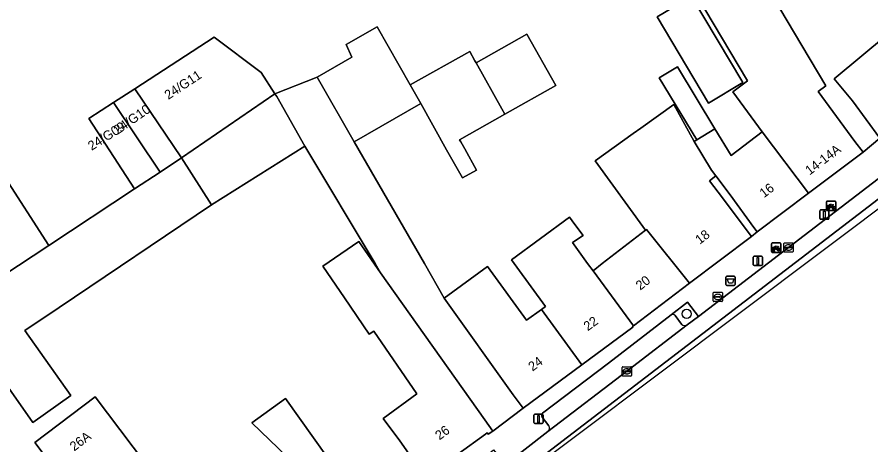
# Model space of a CAD drawing. Extents: x 159371 to 159986, y 382987 to 383597.
# Drawn here: x 159845.8 to 159937.1, y 383230.6 to 383276.3 of the extents above; entities that cross this region are included whole.
import ezdxf

# ---------------------------------------------------------------- set-up
doc = ezdxf.new("R2010")
doc.units = 0
for name, color, linetype in [('IMGEO_Afvalbak', 7, 'Continuous'), ('IMGEO_Boom', 7, 'Continuous'), ('IMGEO_Erf', 7, 'Continuous'), ('IMGEO_Fietsenrek', 7, 'Continuous'), ('IMGEO_Groenvoorziening', 7, 'Continuous'), ('IMGEO_Kolk', 7, 'Continuous'), ('IMGEO_Lichtmast', 7, 'Continuous'), ('IMGEO_Pand', 7, 'Continuous'), ('IMGEO_Pand_nummerreeks', 7, 'Continuous'), ('IMGEO_Parkeervlak_open', 7, 'Continuous'), ('IMGEO_Rijbaan_lokaal_gesloten', 7, 'Continuous'), ('IMGEO_Rijbaan_lokaal_open', 7, 'Continuous'), ('IMGEO_Voetpad_open', 7, 'Continuous')]:
    doc.layers.add(name, color=color, linetype=linetype)

msp = doc.modelspace()

# ---------------------------------------------------------------- linework, layer by layer
at = {"layer": 'IMGEO_Afvalbak'}
for p, q in [((159921.6, 383247.75), (159921.6, 383248.55)), ((159921.6, 383248.55), (159921.6, 383247.75)), ((159921.7, 383248.65), (159922.49, 383248.65)), ((159922.49, 383248.65), (159921.7, 383248.65)), ((159922.59, 383248.55), (159922.59, 383247.75)), ((159922.59, 383247.75), (159922.59, 383248.55)), ((159922.49, 383247.65), (159921.7, 383247.65)), ((159921.7, 383247.65), (159922.49, 383247.65))]:
    msp.add_line(p, q, dxfattribs=at)
msp.add_lwpolyline([(159921.743, 383248.364), (159922.447, 383248.364), (159922.298, 383247.894), (159921.892, 383247.894), (159921.743, 383248.364)], dxfattribs=at)
for centre, start, end in [((159921.7, 383248.55), 90, 180), ((159921.7, 383248.55), 90, 180), ((159922.49, 383248.55), 0, 90), ((159922.49, 383248.55), 360, 90), ((159921.7, 383247.75), 180, 270), ((159921.7, 383247.75), 180, 270), ((159922.49, 383247.75), 270, 0), ((159922.49, 383247.75), 270, 0)]:
    msp.add_arc(centre, 0.1, start, end, dxfattribs=at)
at = {"layer": 'IMGEO_Boom'}
msp.add_circle((159917.394, 383244.613), 0.489, dxfattribs=at)
at = {"layer": 'IMGEO_Erf'}
for points in [[(159916.391, 383295.732), (159929.731, 383273.294), (159932.286, 383268.996), (159931.449, 383268.361), (159935.394, 383263.043), (159936.262, 383261.889), (159938.069, 383263.392), (159935.149, 383267.369), (159933.181, 383269.745), (159938.884, 383274.471)], [(159888.942, 383267.107), (159881.821, 383262.989), (159889.333, 383250), (159891.454, 383246.285), (159896.094, 383249.664), (159900.273, 383243.925), (159901.857, 383245.074), (159902.302, 383245.397), (159899.218, 383249.602), (159898.643, 383250.386), (159904.87, 383254.952), (159905.444, 383254.169), (159906.311, 383252.986), (159905.181, 383252.229), (159906.797, 383250), (159907.379, 383249.229), (159908.37, 383250), (159913, 383253.565), (159907.607, 383260.971), (159911.671, 383263.885), (159912.475, 383264.462), (159916.013, 383266.999), (159918.196, 383263.04), (159918.468, 383263.205), (159914.449, 383269.835), (159916.408, 383271.023), (159920.427, 383264.392), (159922.151, 383261.548), (159925.461, 383264.06), (159922.328, 383268.339), (159923.904, 383269.535), (159910.435, 383292.191)], [(159844.202, 383259.616), (159849.15, 383251.931), (159858.332, 383257.968), (159853.456, 383265.492), (159856.082, 383267.195), (159858.36, 383268.671), (159866.841, 383274.168), (159871.87, 383270.393), (159873.352, 383268.134), (159877.865, 383269.907), (159881.58, 383272.032), (159880.954, 383273.399), (159884.279, 383275.3), (159887.828, 383269.093), (159894.183, 383272.656), (159894.739, 383271.664), (159894.863, 383271.443), (159900.315, 383274.499), (159903.396, 383269.004), (159897.944, 383265.948), (159893.093, 383263.229), (159893.222, 383262.999), (159893.65, 383262.236), (159894.913, 383259.983), (159893.409, 383259.139), (159891.718, 383262.155), (159888.942, 383267.107)], [(159889.569, 383226.993), (159886.701, 383231.03), (159884.934, 383233.432), (159888.517, 383236.07), (159883.921, 383242.774), (159883.447, 383242.45), (159880.783, 383246.335), (159878.465, 383249.715), (159882.326, 383252.361), (159884.643, 383248.981), (159884.072, 383250), (159876.558, 383262.55), (159866.58, 383256.276), (159850.254, 383245.306), (159846.589, 383242.843), (159851.5, 383235.872), (159847.444, 383233.016), (159840.201, 383243.3)], [(159876.562, 383227.528), (159870.877, 383232.977), (159874.49, 383235.552), (159878.98, 383229.251)]]:
    msp.add_lwpolyline(points, dxfattribs=at)
for points in [[(159914.231, 383276.374), (159917.912, 383278.563), (159923.401, 383269.331), (159919.72, 383267.142)], [(159922.053, 383257.339), (159920.52, 383259.358), (159919.823, 383258.822), (159921.228, 383256.998), (159923.862, 383253.482), (159924.314, 383252.884), (159924.928, 383253.367), (159924.582, 383253.827)], [(159854.108, 383235.738), (159860.814, 383226.859), (159854.38, 383222), (159847.675, 383230.879)]]:
    msp.add_lwpolyline(points, close=True, dxfattribs=at)
at = {"layer": 'IMGEO_Fietsenrek'}
for p, q in [((159932.345, 383255.729), (159932.345, 383256.57)), ((159932.345, 383256.57), (159932.345, 383255.729)), ((159932.42, 383256.654), (159933.261, 383256.654)), ((159933.261, 383256.654), (159932.42, 383256.654)), ((159933.345, 383256.579), (159933.345, 383255.738)), ((159933.345, 383255.738), (159933.345, 383256.579)), ((159933.27, 383255.654), (159932.429, 383255.654)), ((159932.429, 383255.654), (159933.27, 383255.654)), ((159932.472, 383255.738), (159932.511, 383255.898)), ((159932.506, 383255.738), (159932.472, 383255.738)), ((159932.541, 383255.886), (159932.506, 383255.738)), ((159932.583, 383255.91), (159932.582, 383255.914)), ((159932.624, 383255.738), (159932.59, 383255.88)), ((159932.614, 383255.921), (159932.615, 383255.914)), ((159932.622, 383255.884), (159932.657, 383255.738)), ((159932.657, 383255.738), (159932.624, 383255.738)), ((159933.032, 383256.203), (159933.068, 383256.108)), ((159926.473, 383251.263), (159926.473, 383252.104)), ((159926.473, 383252.104), (159926.473, 383251.263)), ((159926.548, 383252.188), (159927.389, 383252.188)), ((159927.389, 383252.188), (159926.548, 383252.188)), ((159927.473, 383252.113), (159927.473, 383251.272)), ((159927.473, 383251.272), (159927.473, 383252.113)), ((159927.398, 383251.188), (159926.557, 383251.188)), ((159926.557, 383251.188), (159927.398, 383251.188)), ((159926.6, 383251.272), (159926.639, 383251.432)), ((159926.634, 383251.272), (159926.6, 383251.272)), ((159926.669, 383251.42), (159926.634, 383251.272)), ((159926.711, 383251.444), (159926.71, 383251.448)), ((159926.752, 383251.272), (159926.718, 383251.414)), ((159926.742, 383251.455), (159926.743, 383251.448)), ((159926.75, 383251.418), (159926.785, 383251.272)), ((159926.785, 383251.272), (159926.752, 383251.272)), ((159927.16, 383251.737), (159927.196, 383251.642))]:
    msp.add_line(p, q, dxfattribs=at)
for points in [[(159932.679, 383256.128), (159932.627, 383256.038), (159932.587, 383256.013), (159932.588, 383256.06), (159932.643, 383256.154)], [(159932.658, 383256.18), (159932.753, 383256.344), (159932.839, 383256.33), (159932.841, 383256.321), (159932.785, 383256.31), (159932.758, 383256.265), (159933.014, 383256.224)], [(159932.954, 383255.936), (159932.904, 383255.936), (159932.713, 383256.187), (159932.694, 383256.155)], [(159933.001, 383256.199), (159932.744, 383256.24), (159932.727, 383256.211), (159932.894, 383255.991), (159933.001, 383256.199)], [(159933.049, 383256.101), (159933.019, 383256.178), (159932.91, 383255.96), (159932.953, 383255.96)], [(159932.983, 383255.96), (159933.103, 383255.959), (159933.059, 383256.073)], [(159933.079, 383256.08), (159933.134, 383255.935), (159932.984, 383255.935)], [(159933.014, 383256.224), (159933.039, 383256.273), (159933.033, 383256.277), (159933.01, 383256.281), (159932.998, 383256.288), (159932.997, 383256.291), (159932.999, 383256.296), (159933.094, 383256.281), (159933.096, 383256.271), (159933.086, 383256.258), (159933.074, 383256.252), (159933.06, 383256.258), (159933.032, 383256.203)], [(159926.807, 383251.662), (159926.755, 383251.572), (159926.715, 383251.547), (159926.716, 383251.594), (159926.771, 383251.688)], [(159926.786, 383251.714), (159926.881, 383251.878), (159926.967, 383251.864), (159926.969, 383251.855), (159926.913, 383251.844), (159926.886, 383251.799), (159927.142, 383251.758)], [(159927.082, 383251.47), (159927.032, 383251.47), (159926.841, 383251.721), (159926.822, 383251.689)], [(159927.129, 383251.733), (159926.872, 383251.774), (159926.855, 383251.745), (159927.022, 383251.525), (159927.129, 383251.733)], [(159927.177, 383251.635), (159927.147, 383251.712), (159927.038, 383251.494), (159927.081, 383251.494)], [(159927.111, 383251.494), (159927.231, 383251.493), (159927.187, 383251.607)], [(159927.207, 383251.614), (159927.262, 383251.469), (159927.112, 383251.469)], [(159927.142, 383251.758), (159927.167, 383251.807), (159927.161, 383251.811), (159927.138, 383251.815), (159927.126, 383251.822), (159927.125, 383251.825), (159927.127, 383251.83), (159927.222, 383251.815), (159927.224, 383251.805), (159927.214, 383251.792), (159927.202, 383251.786), (159927.188, 383251.792), (159927.16, 383251.737)]]:
    msp.add_lwpolyline(points, dxfattribs=at)
for centre, radius, start, end in [((159932.423, 383256.576), 0.0779, 92.4484, 184.28452), ((159932.423, 383256.576), 0.0779, 92.4484, 184.28452), ((159933.267, 383256.576), 0.0779, 2.4484, 94.28452), ((159933.267, 383256.576), 0.0779, 2.4484, 94.28452), ((159932.423, 383255.732), 0.0779, 182.4484, 274.28452), ((159932.423, 383255.732), 0.0779, 182.4484, 274.28452), ((159932.585, 383256.039), 0.159, 62.67661, 242.13685), ((159932.585, 383256.039), 0.129, 63.31916, 238.90302), ((159932.565, 383255.91), 0.0499, 12.8025, 158.69338), ((159932.585, 383256.039), 0.159, 253.99666, 271.78671), ((159932.565, 383255.91), 0.0174, 12.8025, 163.45023), ((159932.585, 383256.039), 0.129, 253.41502, 269.02044), ((159932.585, 383256.039), 0.129, 283.60429, 43.43025), ((159932.585, 383256.039), 0.159, 283.5766, 46.60424), ((159933.112, 383255.955), 0.159, 113.3408, 178.32165), ((159933.112, 383255.955), 0.159, 187.0065, 105.77075), ((159933.112, 383255.955), 0.129, 113.92302, 177.95563), ((159933.112, 383255.955), 0.129, 188.67146, 104.58832), ((159933.267, 383255.732), 0.0779, 272.4484, 4.28452), ((159933.267, 383255.732), 0.0779, 272.4484, 4.28452), ((159926.551, 383252.11), 0.0779, 92.4484, 184.28452), ((159926.551, 383252.11), 0.0779, 92.4484, 184.28452), ((159927.395, 383252.11), 0.0779, 2.4484, 94.28452), ((159927.395, 383252.11), 0.0779, 2.4484, 94.28452), ((159926.551, 383251.266), 0.0779, 182.4484, 274.28452), ((159926.551, 383251.266), 0.0779, 182.4484, 274.28452), ((159926.713, 383251.573), 0.159, 62.67661, 242.13685), ((159926.713, 383251.573), 0.129, 63.31916, 238.90302), ((159926.693, 383251.444), 0.0499, 12.8025, 158.69338), ((159926.713, 383251.573), 0.159, 253.99666, 271.78671), ((159926.693, 383251.444), 0.0174, 12.8025, 163.45023), ((159926.713, 383251.573), 0.129, 253.41502, 269.02044), ((159926.713, 383251.573), 0.129, 283.60429, 43.43025), ((159926.713, 383251.573), 0.159, 283.5766, 46.60424), ((159927.24, 383251.489), 0.159, 113.3408, 178.32165), ((159927.24, 383251.489), 0.159, 187.0065, 105.77075), ((159927.24, 383251.489), 0.129, 113.92302, 177.95563), ((159927.24, 383251.489), 0.129, 188.67146, 104.58832), ((159927.395, 383251.266), 0.0779, 272.4484, 4.28452), ((159927.395, 383251.266), 0.0779, 272.4484, 4.28452)]:
    msp.add_arc(centre, radius, start, end, dxfattribs=at)
at = {"layer": 'IMGEO_Groenvoorziening'}
for points in [[(159917.448, 383243.448), (159918.678, 383244.335), (159917.468, 383245.881), (159915.741, 383244.492)], [(159916.171, 383244.455), (159916.844, 383243.527)]]:
    msp.add_lwpolyline(points, dxfattribs=at)
for centre, radius, start, end in [((159915.932, 383244.2), 0.349, 46.87499, 123.28903), ((159917.19, 383243.821), 0.454, 220.36899, 304.72764)]:
    msp.add_arc(centre, radius, start, end, dxfattribs=at)
at = {"layer": 'IMGEO_Kolk'}
for p, q in [((159927.79, 383251.279), (159927.79, 383252.131)), ((159927.865, 383252.205), (159928.717, 383252.205)), ((159928.278, 383251.985), (159928.303, 383251.985)), ((159928.791, 383252.131), (159928.791, 383251.279)), ((159928.717, 383251.205), (159927.865, 383251.205)), ((159928.049, 383251.699), (159928.049, 383251.711)), ((159928.487, 383251.662), (159928.089, 383251.662)), ((159928.092, 383251.748), (159928.49, 383251.748)), ((159928.301, 383251.425), (159928.276, 383251.425)), ((159928.533, 383251.711), (159928.533, 383251.699)), ((159920.227, 383246.003), (159920.227, 383246.855)), ((159920.302, 383246.929), (159921.154, 383246.929)), ((159920.529, 383246.472), (159920.927, 383246.472)), ((159920.715, 383246.709), (159920.74, 383246.709)), ((159921.228, 383246.855), (159921.228, 383246.003)), ((159921.154, 383245.929), (159920.302, 383245.929)), ((159920.486, 383246.423), (159920.486, 383246.435)), ((159920.924, 383246.386), (159920.526, 383246.386)), ((159920.738, 383246.149), (159920.713, 383246.149)), ((159920.97, 383246.435), (159920.97, 383246.423)), ((159910.502, 383238.043), (159910.502, 383238.895)), ((159910.577, 383238.969), (159911.429, 383238.969)), ((159910.761, 383238.463), (159910.761, 383238.475)), ((159911.199, 383238.426), (159910.801, 383238.426)), ((159910.804, 383238.512), (159911.202, 383238.512)), ((159910.99, 383238.749), (159911.015, 383238.749)), ((159911.245, 383238.475), (159911.245, 383238.463)), ((159911.503, 383238.895), (159911.503, 383238.043)), ((159911.429, 383237.969), (159910.577, 383237.969)), ((159911.013, 383238.189), (159910.988, 383238.189))]:
    msp.add_line(p, q, dxfattribs=at)
for points in [[(159927.79, 383251.279), (159927.79, 383252.131)], [(159927.865, 383252.205), (159928.717, 383252.205)], [(159928.791, 383252.131), (159928.791, 383251.279)], [(159928.717, 383251.205), (159927.865, 383251.205)], [(159920.227, 383246.003), (159920.227, 383246.855)], [(159920.302, 383246.929), (159921.154, 383246.929)], [(159921.228, 383246.855), (159921.228, 383246.003)], [(159921.154, 383245.929), (159920.302, 383245.929)], [(159910.502, 383238.043), (159910.502, 383238.895)], [(159910.577, 383238.969), (159911.429, 383238.969)], [(159911.503, 383238.895), (159911.503, 383238.043)], [(159911.429, 383237.969), (159910.577, 383237.969)]]:
    msp.add_lwpolyline(points, dxfattribs=at)
for centre, radius, start, end in [((159927.867, 383252.129), 0.0765, 91.55205, 178.44795), ((159927.867, 383252.129), 0.0765, 91.55205, 178.44795), ((159928.715, 383252.129), 0.0765, 1.55205, 88.44795), ((159928.715, 383252.129), 0.0765, 1.55205, 88.44795), ((159927.867, 383251.281), 0.0765, 181.55205, 268.44795), ((159927.867, 383251.281), 0.0765, 181.55205, 268.44795), ((159928.089, 383251.708), 0.0403, 85.87752, 175.75265), ((159928.086, 383251.698), 0.0366, 178.93798, 274.71019), ((159928.49, 383251.705), 0.043, 264.86636, 352.45326), ((159928.494, 383251.71), 0.0386, 1.73085, 96.63898), ((159928.715, 383251.281), 0.0765, 271.55205, 358.44795), ((159928.715, 383251.281), 0.0765, 271.55205, 358.44795), ((159920.304, 383246.853), 0.0765, 91.55205, 178.44795), ((159920.304, 383246.853), 0.0765, 91.55205, 178.44795), ((159920.526, 383246.432), 0.0403, 85.87752, 175.75265), ((159920.931, 383246.434), 0.0386, 1.73085, 96.63898), ((159921.152, 383246.853), 0.0765, 1.55205, 88.44795), ((159921.152, 383246.853), 0.0765, 1.55205, 88.44795), ((159920.304, 383246.005), 0.0765, 181.55205, 268.44795), ((159920.304, 383246.005), 0.0765, 181.55205, 268.44795), ((159920.523, 383246.422), 0.0366, 178.93798, 274.71019), ((159920.927, 383246.429), 0.043, 264.86636, 352.45326), ((159921.152, 383246.005), 0.0765, 271.55205, 358.44795), ((159921.152, 383246.005), 0.0765, 271.55205, 358.44795), ((159910.579, 383238.893), 0.0765, 91.55205, 178.44795), ((159910.579, 383238.893), 0.0765, 91.55205, 178.44795), ((159910.801, 383238.472), 0.0403, 85.87752, 175.75265), ((159910.798, 383238.462), 0.0366, 178.93798, 274.71019), ((159911.202, 383238.469), 0.043, 264.86636, 352.45326), ((159911.206, 383238.474), 0.0386, 1.73085, 96.63898), ((159911.427, 383238.893), 0.0765, 1.55205, 88.44795), ((159911.427, 383238.893), 0.0765, 1.55205, 88.44795), ((159910.579, 383238.045), 0.0765, 181.55205, 268.44795), ((159910.579, 383238.045), 0.0765, 181.55205, 268.44795), ((159911.427, 383238.045), 0.0765, 271.55205, 358.44795), ((159911.427, 383238.045), 0.0765, 271.55205, 358.44795)]:
    msp.add_arc(centre, radius, start, end, dxfattribs=at)
for centre, major_axis, ratio, start_param, end_param in [((159928.277, 383251.705), (-0.387, 0.002), 0.722429, 4.712389, 7.853982), ((159928.302, 383251.705), (-0.39, 0.002), 0.717154, 1.570796, 4.712389), ((159920.714, 383246.429), (-0.387, 0.002), 0.722429, 4.712389, 7.853982), ((159920.739, 383246.429), (-0.39, 0.002), 0.717154, 1.570796, 4.712389), ((159910.989, 383238.469), (-0.387, 0.002), 0.722429, 4.712389, 7.853982), ((159911.014, 383238.469), (-0.39, 0.002), 0.717154, 1.570796, 4.712389)]:
    msp.add_ellipse(centre, major_axis=major_axis, ratio=ratio, start_param=start_param, end_param=end_param, dxfattribs=at)
at = {"layer": 'IMGEO_Lichtmast'}
for p, q in [((159931.631, 383254.819), (159931.631, 383255.619)), ((159931.631, 383255.619), (159931.631, 383254.819)), ((159931.731, 383255.719), (159932.521, 383255.719)), ((159932.521, 383255.719), (159931.731, 383255.719)), ((159932.621, 383255.619), (159932.621, 383254.819)), ((159932.621, 383254.819), (159932.621, 383255.619)), ((159932.521, 383254.719), (159931.731, 383254.719)), ((159931.731, 383254.719), (159932.521, 383254.719)), ((159924.506, 383249.871), (159924.506, 383250.671)), ((159924.506, 383250.671), (159924.506, 383249.871)), ((159924.606, 383250.771), (159925.396, 383250.771)), ((159925.396, 383250.771), (159924.606, 383250.771)), ((159925.496, 383250.671), (159925.496, 383249.871)), ((159925.496, 383249.871), (159925.496, 383250.671)), ((159925.396, 383249.771), (159924.606, 383249.771)), ((159924.606, 383249.771), (159925.396, 383249.771)), ((159901.055, 383232.991), (159901.055, 383233.791)), ((159901.055, 383233.791), (159901.055, 383232.991)), ((159901.155, 383233.891), (159901.945, 383233.891)), ((159901.945, 383233.891), (159901.155, 383233.891)), ((159902.045, 383233.791), (159902.045, 383232.991)), ((159902.045, 383232.991), (159902.045, 383233.791)), ((159901.945, 383232.891), (159901.155, 383232.891)), ((159901.155, 383232.891), (159901.945, 383232.891))]:
    msp.add_line(p, q, dxfattribs=at)
for points in [[(159932.051, 383255.594), (159932.201, 383255.594), (159932.201, 383254.844), (159932.051, 383254.844), (159932.051, 383255.594)], [(159924.926, 383250.646), (159925.076, 383250.646), (159925.076, 383249.896), (159924.926, 383249.896), (159924.926, 383250.646)], [(159901.475, 383233.766), (159901.625, 383233.766), (159901.625, 383233.016), (159901.475, 383233.016), (159901.475, 383233.766)]]:
    msp.add_lwpolyline(points, dxfattribs=at)
for centre, start, end in [((159931.731, 383255.619), 90, 180), ((159931.731, 383255.619), 90, 180), ((159932.521, 383255.619), 0, 90), ((159932.521, 383255.619), 360, 90), ((159931.731, 383254.819), 180, 270), ((159931.731, 383254.819), 180, 270), ((159932.521, 383254.819), 270, 0), ((159932.521, 383254.819), 270, 0), ((159924.606, 383250.671), 90, 180), ((159924.606, 383250.671), 90, 180), ((159925.396, 383250.671), 0, 90), ((159925.396, 383250.671), 360, 90), ((159924.606, 383249.871), 180, 270), ((159924.606, 383249.871), 180, 270), ((159925.396, 383249.871), 270, 0), ((159925.396, 383249.871), 270, 0), ((159901.155, 383233.791), 90, 180), ((159901.155, 383233.791), 90, 180), ((159901.945, 383233.791), 0, 90), ((159901.945, 383233.791), 360, 90), ((159901.155, 383232.991), 180, 270), ((159901.155, 383232.991), 180, 270), ((159901.945, 383232.991), 270, 0), ((159901.945, 383232.991), 270, 0)]:
    msp.add_arc(centre, 0.1, start, end, dxfattribs=at)
at = {"layer": 'IMGEO_Pand'}
for points in [[(159916.391, 383295.732), (159913.836, 383300.03), (159907.88, 383296.489), (159908.686, 383295.134), (159910.435, 383292.191), (159923.904, 383269.535), (159922.328, 383268.339), (159925.461, 383264.06), (159930.434, 383257.507), (159936.262, 383261.889), (159935.394, 383263.043), (159931.449, 383268.361), (159932.286, 383268.996), (159929.731, 383273.294)], [(159917.912, 383278.563), (159914.231, 383276.374), (159919.72, 383267.142), (159923.401, 383269.331)], [(159887.828, 383269.093), (159884.279, 383275.3), (159880.954, 383273.399), (159881.58, 383272.032), (159877.865, 383269.907), (159881.821, 383262.989), (159888.942, 383267.107)], [(159873.352, 383268.134), (159871.87, 383270.393), (159866.841, 383274.168), (159858.36, 383268.671), (159863.344, 383261.297)], [(159894.863, 383271.443), (159897.612, 383266.54), (159897.944, 383265.948), (159903.396, 383269.004), (159900.315, 383274.499)], [(159938.884, 383274.471), (159933.181, 383269.745), (159935.149, 383267.369), (159938.069, 383263.392), (159944.004, 383268.292)], [(159894.863, 383271.443), (159894.739, 383271.664), (159894.183, 383272.656), (159887.828, 383269.093), (159888.942, 383267.107), (159891.718, 383262.155), (159893.409, 383259.139), (159894.913, 383259.983), (159893.65, 383262.236), (159893.222, 383262.999), (159893.093, 383263.229), (159897.944, 383265.948), (159897.612, 383266.54)], [(159914.449, 383269.835), (159918.468, 383263.205), (159920.427, 383264.392), (159916.408, 383271.023)], [(159856.082, 383267.195), (159861.058, 383259.76), (159863.344, 383261.297), (159858.36, 383268.671)], [(159866.58, 383256.276), (159876.558, 383262.55), (159873.535, 383267.856), (159873.352, 383268.134), (159863.344, 383261.297)], [(159856.082, 383267.195), (159853.456, 383265.492), (159858.332, 383257.968), (159861.058, 383259.76)], [(159919.823, 383258.822), (159920.52, 383259.358), (159920.061, 383259.963), (159918.196, 383263.04), (159916.013, 383266.999), (159912.475, 383264.462), (159911.671, 383263.885), (159907.607, 383260.971), (159913, 383253.565), (159913.087, 383253.632), (159917.716, 383247.898), (159924.314, 383252.884), (159923.862, 383253.482), (159921.228, 383256.998)], [(159925.461, 383264.06), (159922.151, 383261.548), (159920.427, 383264.392), (159918.468, 383263.205), (159918.196, 383263.04), (159920.061, 383259.963), (159920.52, 383259.358), (159922.053, 383257.339), (159924.582, 383253.827), (159924.928, 383253.367), (159930.434, 383257.507)], [(159866.58, 383256.276), (159863.344, 383261.297), (159861.058, 383259.76), (159858.332, 383257.968), (159849.15, 383251.931), (159840.957, 383246.545), (159837.698, 383244.402), (159838.941, 383242.708), (159839.084, 383242.514), (159840.201, 383243.3), (159847.444, 383233.016), (159851.5, 383235.872), (159846.589, 383242.843), (159850.254, 383245.306)], [(159844.202, 383259.616), (159837.09, 383255.036), (159840.957, 383246.545), (159849.15, 383251.931)], [(159907.379, 383249.229), (159906.797, 383250), (159905.181, 383252.229), (159906.311, 383252.986), (159905.444, 383254.169), (159904.87, 383254.952), (159898.643, 383250.386), (159899.218, 383249.602), (159902.302, 383245.397), (159901.857, 383245.074), (159906.181, 383239.17), (159911.635, 383243.207), (159911.587, 383243.271), (159911.692, 383243.35)], [(159913.087, 383253.632), (159913, 383253.565), (159908.37, 383250), (159907.379, 383249.229), (159911.692, 383243.35), (159917.716, 383247.898)], [(159884.643, 383248.981), (159882.326, 383252.361), (159878.465, 383249.715), (159880.783, 383246.335), (159883.447, 383242.45), (159883.921, 383242.774), (159888.517, 383236.07), (159884.934, 383233.432), (159886.701, 383231.03), (159889.569, 383226.993), (159890.046, 383227.35), (159889.944, 383227.479), (159895.862, 383231.751), (159896.057, 383231.892), (159896.175, 383231.743), (159896.67, 383232.088), (159895.805, 383233.284)], [(159901.857, 383245.074), (159900.273, 383243.925), (159896.094, 383249.664), (159891.454, 383246.285), (159898.839, 383235.976), (159899.898, 383234.52), (159906.181, 383239.17)], [(159854.38, 383222), (159860.814, 383226.859), (159854.108, 383235.738), (159847.675, 383230.879)], [(159878.98, 383229.251), (159874.49, 383235.552), (159870.877, 383232.977), (159876.562, 383227.528), (159875.367, 383226.676), (159872.459, 383224.604), (159877.122, 383218.059), (159883.516, 383222.686), (159883.37, 383222.888), (159880.771, 383226.738)]]:
    msp.add_lwpolyline(points, close=True, dxfattribs=at)
at = {"layer": 'IMGEO_Parkeervlak_open'}
for points in [[(159915.741, 383244.492), (159909.025, 383239.354), (159901.983, 383233.992)], [(159916.844, 383243.527), (159916.171, 383244.455)], [(159902.531, 383232.027), (159911.142, 383238.598), (159917.448, 383243.448)], [(159901.942, 383233.576), (159902.663, 383232.656)]]:
    msp.add_lwpolyline(points, dxfattribs=at)
for centre, radius, start, end in [((159915.932, 383244.2), 0.349, 46.87499, 123.28903), ((159917.19, 383243.821), 0.454, 220.36899, 304.72764), ((159902.147, 383233.766), 0.279, 125.97116, 222.77132), ((159902.216, 383232.422), 0.505, 308.63516, 27.66099)]:
    msp.add_arc(centre, radius, start, end, dxfattribs=at)
at = {"layer": 'IMGEO_Rijbaan_lokaal_gesloten'}
msp.add_lwpolyline([(159881.821, 383262.989), (159877.865, 383269.907), (159873.352, 383268.134), (159873.535, 383267.856), (159876.558, 383262.55), (159884.072, 383250), (159884.643, 383248.981), (159895.805, 383233.284), (159896.67, 383232.088), (159899.898, 383234.52), (159898.839, 383235.976), (159891.454, 383246.285), (159889.333, 383250)], close=True, dxfattribs=at)
for points in [[(159880.097, 383213.321), (159888.449, 383219.325), (159894.22, 383223.535), (159897.491, 383225.958), (159949.02, 383265.371)], [(159938.953, 383259.858), (159928.303, 383251.721), (159918.678, 383244.335), (159917.448, 383243.448), (159911.142, 383238.598), (159902.531, 383232.027), (159898.003, 383228.514)]]:
    msp.add_lwpolyline(points, dxfattribs=at)
at = {"layer": 'IMGEO_Rijbaan_lokaal_open'}
msp.add_lwpolyline([(159782.678, 383149.411), (159870.405, 383205.208), (159949.617, 383264.636), (159949.02, 383265.371), (159897.491, 383225.958), (159894.22, 383223.535), (159888.449, 383219.325), (159880.097, 383213.321)], dxfattribs=at)
at = {"layer": 'IMGEO_Voetpad_open'}
for points in [[(159938.069, 383263.392), (159936.262, 383261.889), (159930.434, 383257.507), (159924.928, 383253.367), (159924.314, 383252.884), (159917.716, 383247.898), (159911.692, 383243.35), (159911.587, 383243.271), (159911.635, 383243.207), (159906.181, 383239.17), (159899.898, 383234.52), (159896.67, 383232.088), (159896.175, 383231.743), (159896.057, 383231.892), (159895.862, 383231.751), (159889.944, 383227.479)], [(159901.983, 383233.992), (159909.025, 383239.354), (159915.741, 383244.492), (159917.468, 383245.881), (159918.678, 383244.335), (159928.303, 383251.721), (159938.953, 383259.858)], [(159902.663, 383232.656), (159901.942, 383233.576)], [(159891.083, 383225.86), (159895.126, 383228.814), (159896.721, 383230.096), (159898.003, 383228.514), (159902.531, 383232.027)]]:
    msp.add_lwpolyline(points, dxfattribs=at)
for centre, radius, start, end in [((159902.147, 383233.766), 0.279, 125.97116, 222.77132), ((159902.216, 383232.422), 0.505, 308.63516, 27.66099)]:
    msp.add_arc(centre, radius, start, end, dxfattribs=at)

# ---------------------------------------------------------------- texts
at = {"layer": 'IMGEO_Pand_nummerreeks'}
for s, rotation, p in [('24/G11', 33.52852, (159861.949, 383267.47)), ('24/G10', 34.77783, (159856.525, 383263.744)), ('24/G09', 32.22888, (159853.739, 383262.032)), ('14-14A', 37.19069, (159930.554, 383259.397)), ('16', 37.19642, (159925.666, 383256.968)), ('18', 37.60322, (159918.794, 383251.991)), ('20', 37.60895, (159912.431, 383247.09)), ('22', 36.06196, (159906.819, 383242.744)), ('24', 36.06196, (159900.907, 383238.439)), ('26A', 37.00253, (159851.876, 383229.895)), ('26', 36.35417, (159890.951, 383231.079))]:
    msp.add_text(s, height=1, rotation=rotation, dxfattribs=at).set_placement(p)

doc.saveas('drawing.dxf')
